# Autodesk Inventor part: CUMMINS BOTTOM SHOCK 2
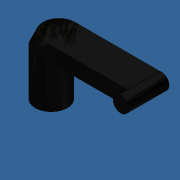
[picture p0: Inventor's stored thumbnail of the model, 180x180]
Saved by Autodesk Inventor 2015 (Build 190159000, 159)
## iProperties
Created: 2014-10
Part Number: CUMMINS BOTTOM SHOCK 2
Material: Generic
Document SubType Name: Modeling
Designer: caovt
Density: 1 g/cm^3
Appearance: Default
Author: caovt
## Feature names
1. Extrusion1
2. Extrusion2
3. Sweep1
4. Extrusion6
5. Extrusion7
## Parameters: d0 = 4.572 mm, d1 = 27.94 mm, d2 = 20.35054 mm, d3 = 25.65051 mm, d4 = 9.525 mm, d5 = 0, d6 = 9.525 mm, d7 = 13.97 mm, d8 = 0, d9 = 0, d10 = 0, d24 = 4.699 mm, d25 = 2.54 mm, d26 = 39.6875 mm, d27 = 0, d28 = 0, d29 = 25.4 mm, d30 = 0
